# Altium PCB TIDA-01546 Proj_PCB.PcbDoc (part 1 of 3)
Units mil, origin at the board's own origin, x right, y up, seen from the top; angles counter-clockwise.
Board outline 2500 x 2000 mil, 2 copper layers (Top Layer, Bottom Layer), stack 62 mil thick; 176 components, 113 nets, 564 pads, 250 vias.
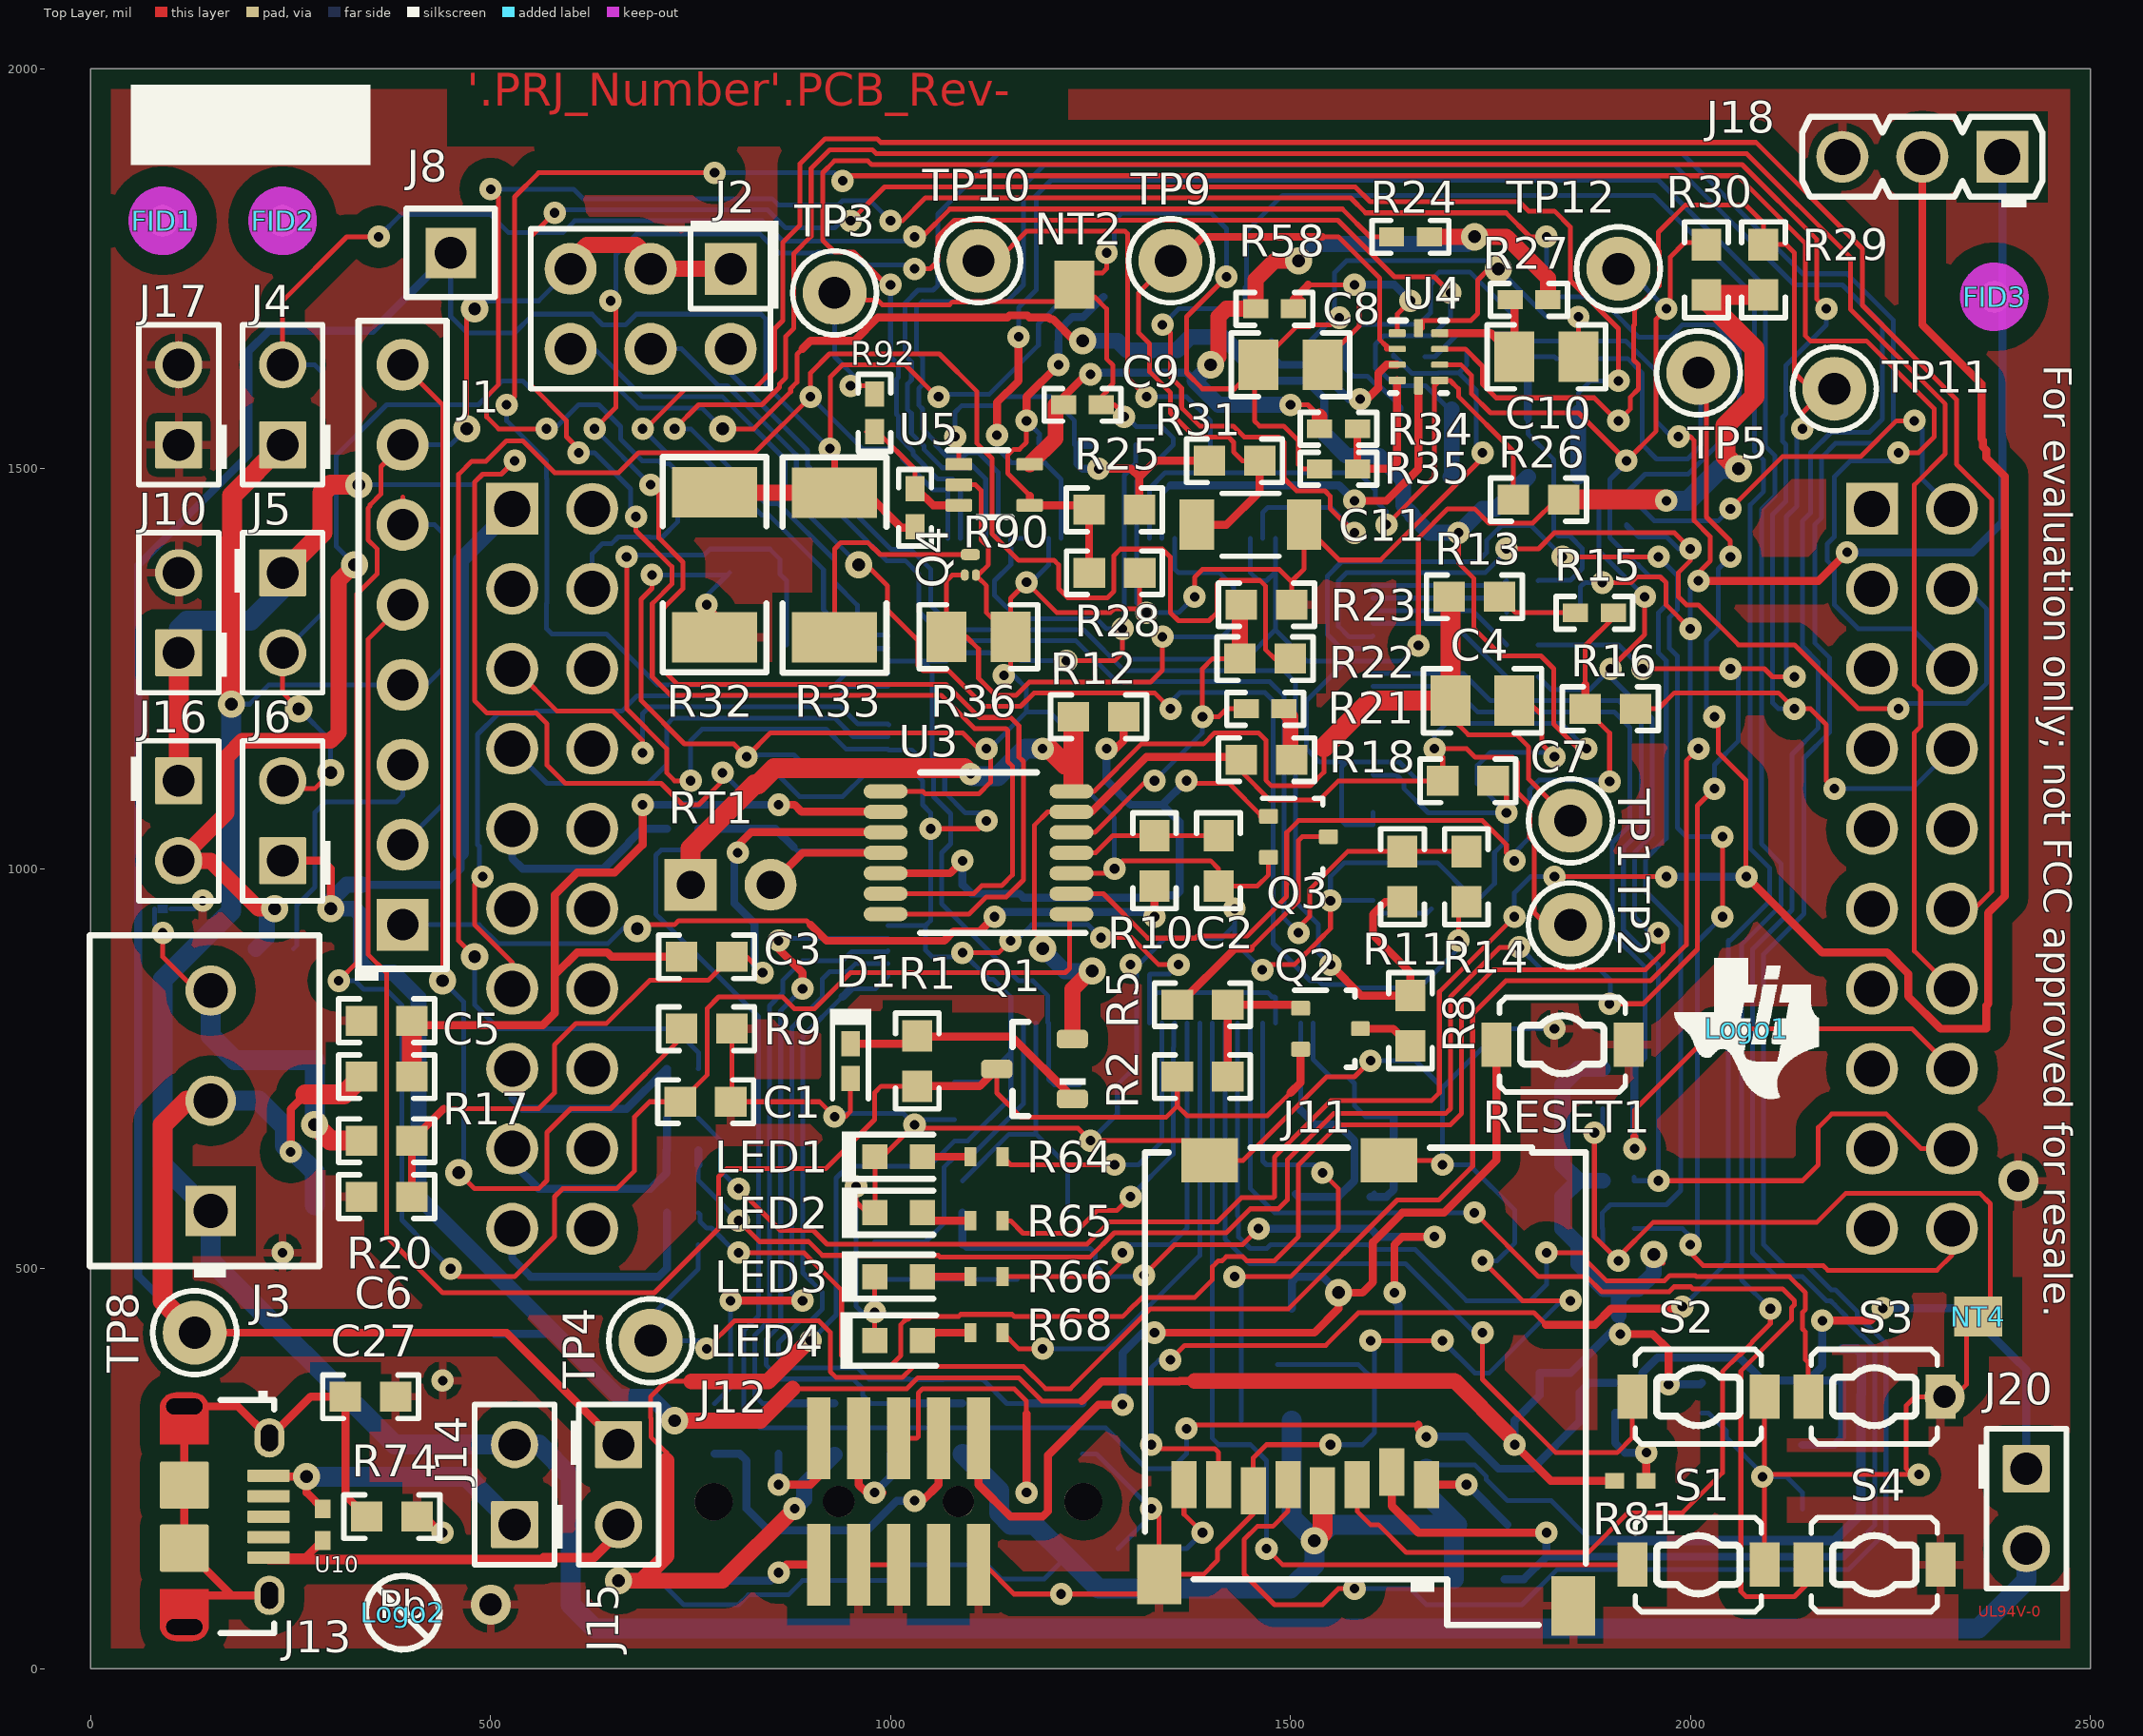
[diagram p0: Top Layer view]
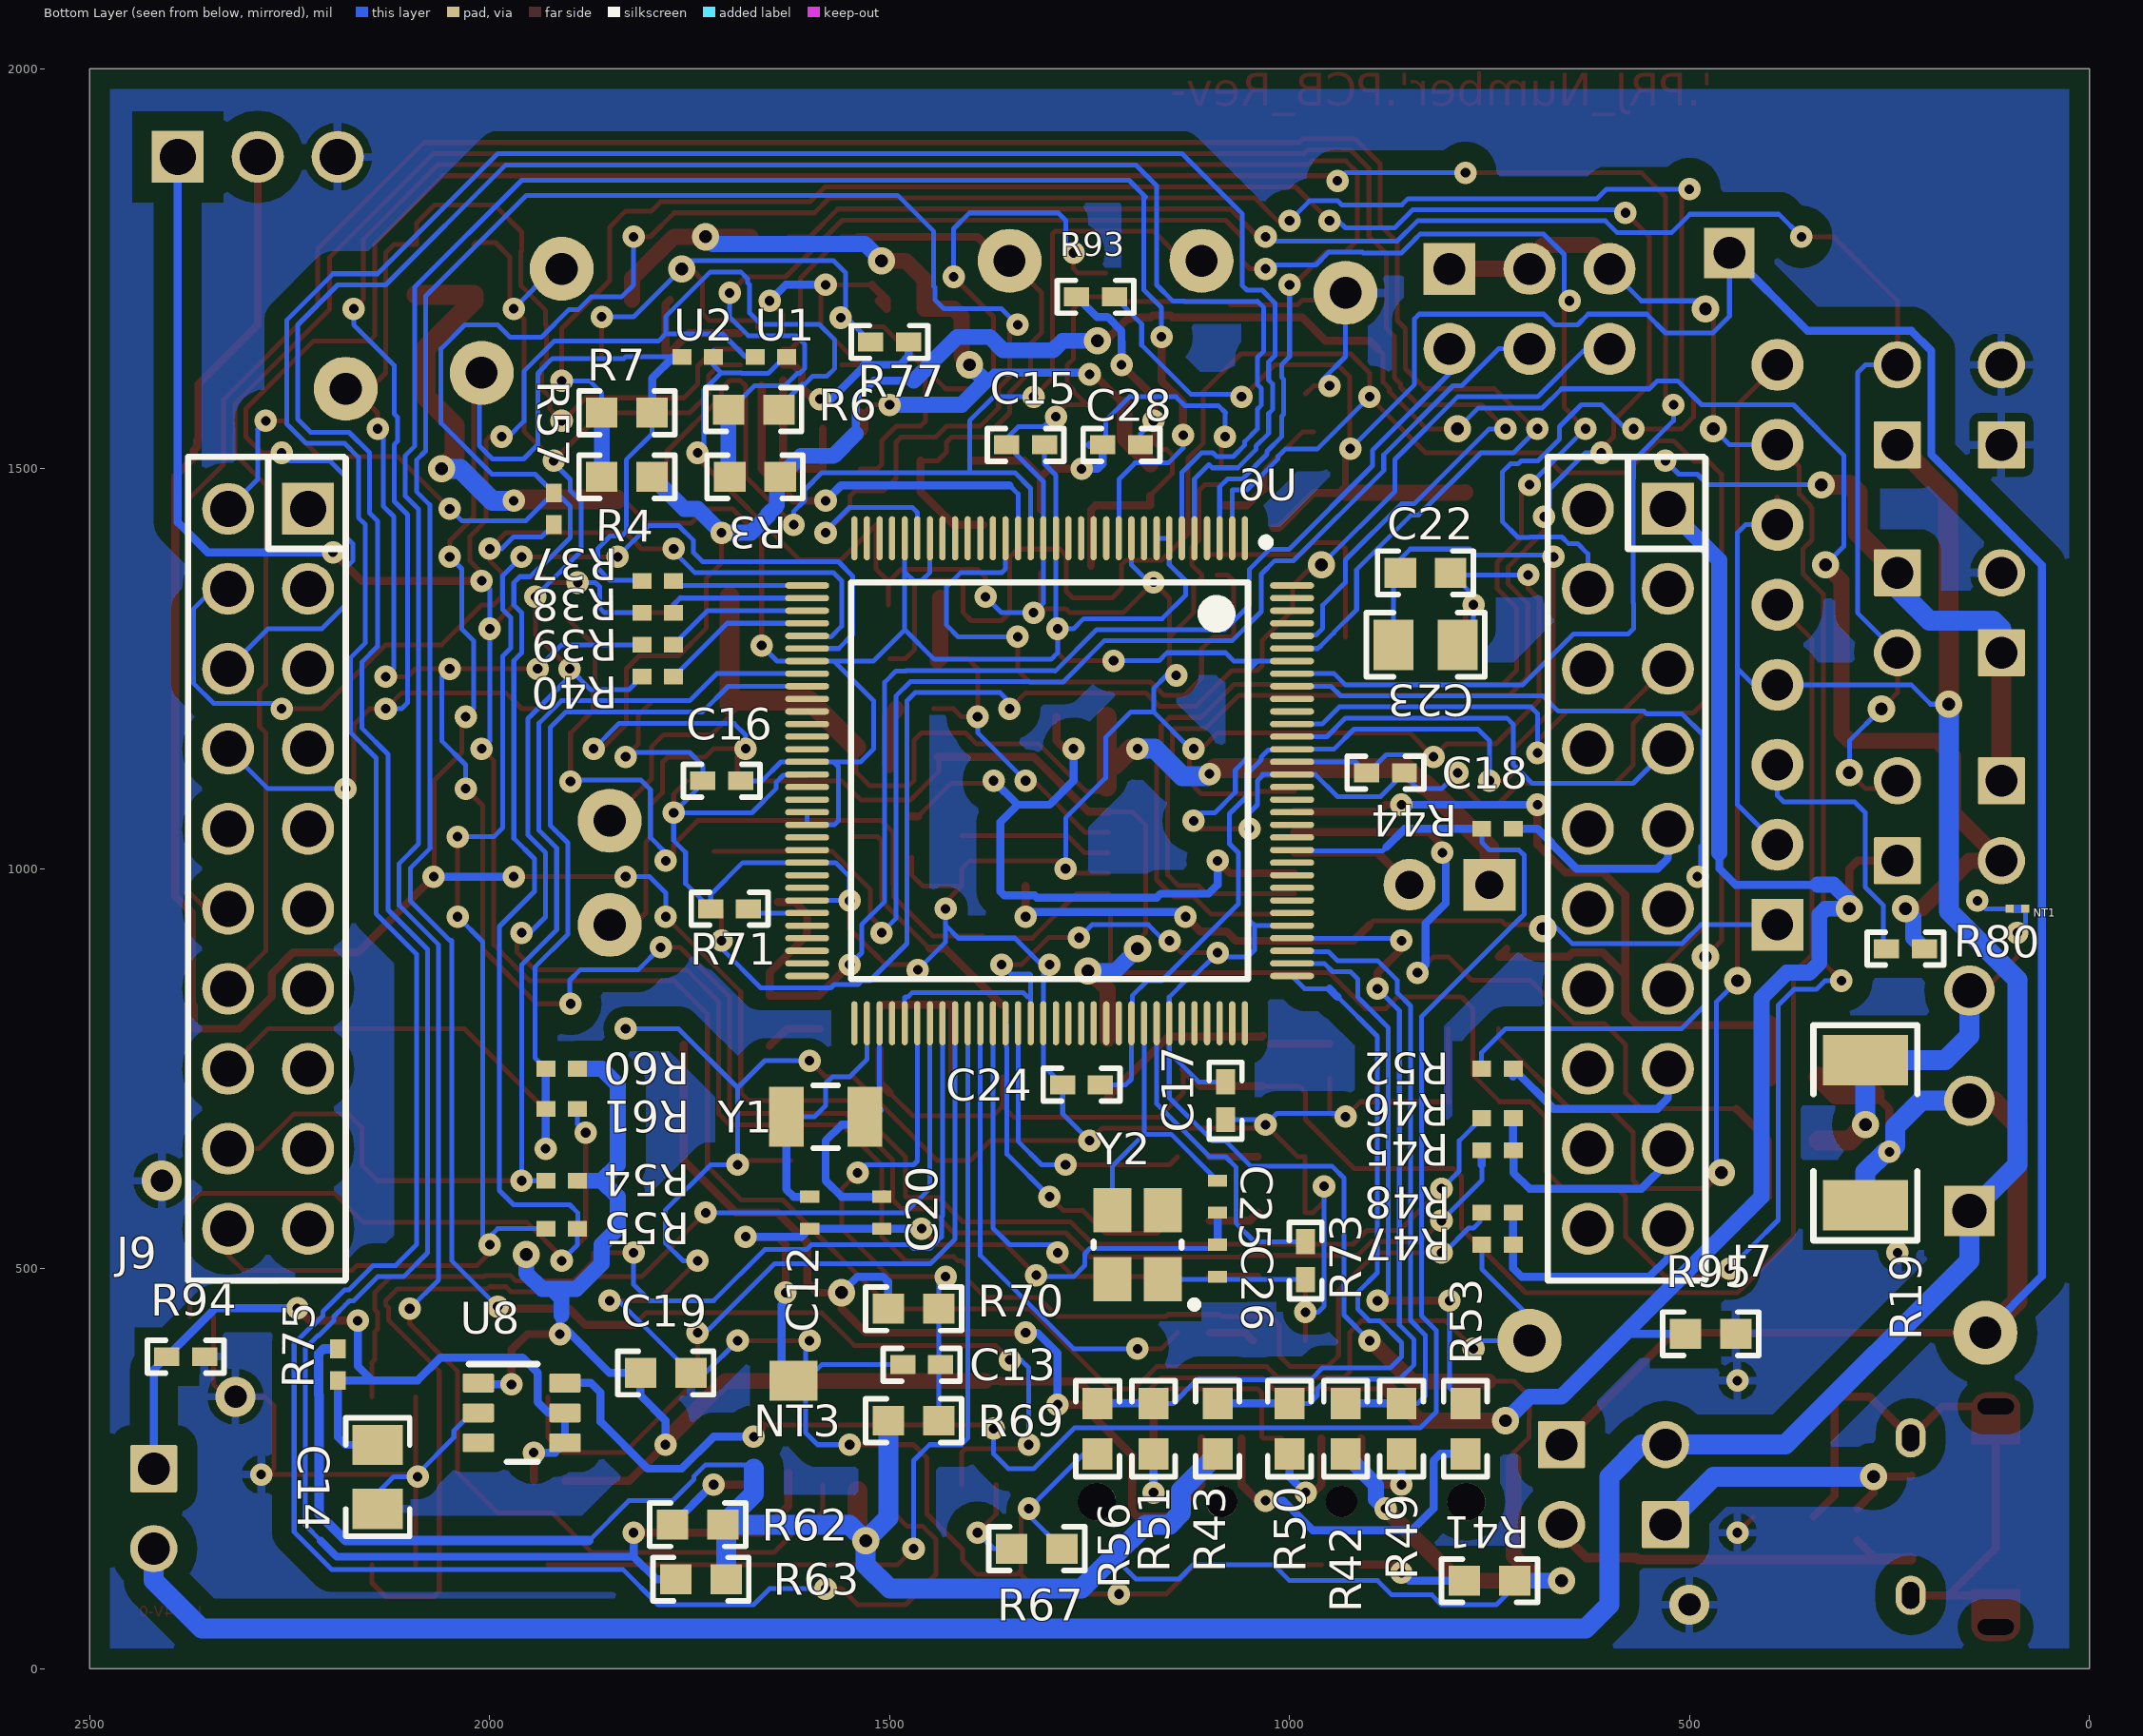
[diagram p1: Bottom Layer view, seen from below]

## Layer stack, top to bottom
Top Solder: solder mask 0.4, Solder Resist, Dk 3.5
Top Layer: signal copper 1.4
Dielectric1: core 59.2, FR-4, Dk 4.8
Bottom Layer: signal copper 1.4
Bottom Solder: solder mask 0.4, Solder Resist, Dk 3.5

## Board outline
0,0 2500,0 2500,2000 0,2000

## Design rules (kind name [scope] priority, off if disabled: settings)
AcuteAngle [All] p1: minimum=4.50000000000000E+0001 checktracksonly=FALSE
AssemblyTestPointUsage [All] p1: valid=2
BoardOutlineClearance BoardOutlineClearance_MountingHoles [OnCopper and InComponentClass('Mounting Holes')] p1: gap=40
BoardOutlineClearance BoardOutlineClearance_Poly [OnCopper and IsPoly] p2: gap=25
BoardOutlineClearance [OnCopper and Not InComponentClass('Logo') and not InComponentClass('FiducialMark') and not InRegion(1000,500,4000,800) and not InPoly] p3: gap=75 except(30: Arc-OutlineEdge Track-OutlineEdge SMDPad-OutlineEdge THPad-OutlineEdge Via-OutlineEdge Fill-OutlineEdge Poly-OutlineEdge Region-OutlineEdge Text-OutlineEdge)
Clearance Clearance_Keepouts [((IsTrack Or IsArc) And Not InPoly) And IsFree and IsKeepOut vs ((IsTrack Or IsArc) And Not InPoly) And IsFree and IsKeepOut] p1: gap=0
Clearance Clearance_Poly [InPolygon] p2: gap=25
Clearance Clearance_FiducialMark [IsKeepOut and InComponentClass('FiducialMark') vs IsPad and InComponentClass('FiducialMark')] p3: gap=0
Clearance [All] p4: gap=7.87
ComponentClearance ComponentClearance_MountingHoles_FiducialMarks [InComponentClass('Mounting Holes') vs InComponentClass('FiducialMark')] p1: gap=50 collisioncheckmode=3 verticalgap=10 showdistances=FALSE
ComponentClearance ComponentClearance_Shunt [InComponentClass('Header') vs InComponentClass('Shunt')] p2: gap=0 collisioncheckmode=3 verticalgap=0 showdistances=FALSE
ComponentClearance ComponentClearance_Logo [InComponentClass('Logo')] p3: gap=50 collisioncheckmode=3 verticalgap=10 showdistances=FALSE
ComponentClearance ComponentClearance_ScrewToNut [(HasFootprint('NY PMS 440 0025 PH')) vs (HasFootprint('Keystone_1902C'))] p4: gap=5 collisioncheckmode=3 verticalgap=10 showdistances=FALSE
ComponentClearance ComponentClearance_MountingHoles [InComponentClass('Mounting Holes')] p5: gap=250 collisioncheckmode=3 verticalgap=100000 showdistances=FALSE
ComponentClearance ComponentClearance_SmallPassives [HasFootprint('0201*') or HasFootprint('0402*') or HasFootprint('0508') or HasFootprint('0603*') or HasFootprint('0612') or HasFootprint('0805*') or HasFootprint('0815*') or HasFootprint('0830*') or HasFootprint('1206*') or HasFootprint('1210*') or HasFootprint('1808*') or HasFootprint('1812*') or HasFootprint('1825*') or HasFootprint('2010*') or HasFootprint('2220*') or HasFootprint('2225*') or HasFootprint('2512*') or HasFootprint('2728*') or HasFootprint('3518*') vs HasFootprint('0201*') or HasFootprint('0402*') or HasFootprint('0508') or HasFootprint('0603*') or HasFootprint('0612') or HasFootprint('0805*') or HasFootprint('0815*') or HasFootprint('0830*') or HasFootprint('1206*') or HasFootprint('1210*') or HasFootprint('1808*') or HasFootprint('1812*') or HasFootprint('1825*') or HasFootprint('2010*') or HasFootprint('2220*') or HasFootprint('2225*') or HasFootprint('2512*') or HasFootprint('2728*') or HasFootprint('3518*')] p6: gap=14.96 collisioncheckmode=3 verticalgap=10 showdistances=FALSE
ComponentClearance ComponentClearance_THtoSMT [IsThruComponent vs IsSMTComponent] p7: gap=40 collisioncheckmode=3 verticalgap=30 showdistances=FALSE
ComponentClearance ComponentClearance_THtoTH [IsThruComponent vs IsThruComponent] p8: gap=30 collisioncheckmode=3 verticalgap=30 showdistances=FALSE
ComponentClearance [All] p9: gap=30 collisioncheckmode=3 verticalgap=10 showdistances=FALSE
DiffPairsRouting [All] p1: maxlimit=100 minlimit=10 mostfreqgap=10 toplayer_minwidth=15 toplayer_maxwidth=15 toplayer_prefwidth=15 bottomlayer_minwidth=15 bottomlayer_maxwidth=15 bottomlayer_prefwidth=15 maxuncoupledlength=1000
FabricationTestPointUsage TestPointUsage [All] p1: valid=2 allowmultiple=FALSE
FabricationTestpoint Testpoint [All] p1: side=3 testpointundercomponent=TRUE minsize=40 maxsize=100 preferedsize=60 minholesize=0 maxholesize=40 preferedholesize=32 testpointgrid=1 allowsidetop=TRUE allowsidebottom=TRUE usegrid=TRUE gridtolerance=0.01
FanoutControl Fanout_LCC [IsLCC] p1: bgadir=Out bgaviamode=Centered fanoutstyle=Auto fanoutdirection=Alternating viagrid=1 // Fanout_LCC (Default Rule)
FanoutControl Fanout_BGA [IsBGA] p2: bgadir=Out bgaviamode=Centered fanoutstyle=Auto fanoutdirection=Alternating viagrid=1 // Fanout_BGA (Default Rule)
FanoutControl Fanout_Default [All] p4: bgadir=Out bgaviamode=Centered fanoutstyle=Auto fanoutdirection=Alternating viagrid=1 // Fanout_Default (Default Rule)
FanoutControl Fanout_Small [(CompPinCount < 5)] p5: bgadir=Out bgaviamode=Centered fanoutstyle=Auto fanoutdirection=OutThenIn viagrid=1 // Fanout_Small (Default Rule)
HoleSize [All] p1: absolutevalues=TRUE maxlimit=251 minlimit=7.87 maxpercent=80.000 minpercent=20.000
MinimumAnnularRing MinimumAnnularRing_ThermalPadVias [IsVia and InAnyComponent] p1: minimumring=5.91
MinimumAnnularRing [All] p2: minimumring=8
MinimumSolderMaskSliver MinimumSolderMaskSliver_Logo [InComponentClass('Logo') vs InComponentClass('Logo')] p1: minsoldermaskwidth=0.7
MinimumSolderMaskSliver [All] p2: minsoldermaskwidth=3.94
PlaneConnect [All] p1: planeconnectstyle=Relief reliefexpansion=10 reliefentries=4 reliefconductorwidth=10 reliefairgap=10
PolygonConnect [All] p1: connectstyle=Relief reliefconductorwidth=10 reliefentries=4 polygonreliefangle="90 Angle" airgapwidth=10
RoutingVias ThermalPadVias [IsVia and InAnyComponent] p1: holewidth=7.87 width=19.68 viastyle="Through Hole" minholewidth=7.87 minwidth=19.68 maxholewidth=12.99 maxwidth=23.62
RoutingVias [All] p2: holewidth=16 width=34 viastyle="Through Hole" minholewidth=7.87 minwidth=26 maxholewidth=40 maxwidth=65
SilkToBoardRegionClearance [Not ((IsComment or IsDesignator) And (Hide <> 'False')) and not InRegion(1000,500,4000,800)] p1:
SilkToSilkClearance SilkToSilkClearance_Pb-FreeLogo [(HasFootprint('Pb-Free_Overlay_Medium') OR HasFootprint('Pb-Free_Overlay_Small')) vs (HasFootprint('Pb-Free_Overlay_Medium') OR HasFootprint('Pb-Free_Overlay_Small'))] p1: silktosilkclearance=0
SilkToSilkClearance [All] p2: silktosilkclearance=4
SilkToSolderMaskClearance SilkToComponentPadClearance [(IsPad or IsFill or IsRegion) and InAnycomponent] p1: minsilkscreentomaskgap=5 clearancetoexposedcopper=TRUE
SilkToSolderMaskClearance "Silk to Solder Mask Opening" [All] p2: minsilkscreentomaskgap=4 clearancetoexposedcopper=FALSE
SolderMaskExpansion [All] p1: expansion=1.97
Width [All] p1: maxlimit=100 minlimit=6 preferedwidth=10 checkconnectedcopper=TRUE
15 further rules are at their usual default settings.

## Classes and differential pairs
component class AssemblyNote: ZZ1 ZZ2 ZZ3 ZZ4
component class FiducialMark: FID1 FID2 FID3
component class "TIDA-01546 Proj_EVM_Hardware": FID1 FID2 FID3 Logo1 Logo2 Logo3 ZZ1 ZZ2 ZZ3 ZZ4
component class Logo: Logo1
component class Header: J1 J2 J4 J5 J6 J10 J14 J15 J16 J17 J18 J20
component class "TIDA-01546 Proj_BatMonitoring": C1 C2 C3 C4 C5 C6 C7 D1 J1 J2 J3 J16 J18 NT1 Q1 Q2 Q3 R1 R2 R3 R4 R5 R6 R7 R8 R9 R10 R11 R12 R13 R14 R15 R16 R17 R18 R19 R20 R21 R22 R23 R80 RT1 TP1 TP2 TP3 TP4 TP5 TP8 U1 U2 U3
component class "TIDA-01546 Proj_SysLoad": C12 C13 C14 C15 C16 C17 C18 C19 C20 C22 C23 C24 C25 C26 C27 J7 J9 J10 J11 J12 J13 J14 J15 J17 J20 LED1 LED2 LED3 LED4 NT3 NT4 R37 R38 R39 R40 R41 R42 R43 R44 R45 R46 R47 R48 R49 R50 R51 R52 R53 R54 R55 R56 R57 R60 R61 R62 R63 R64 R65 R66 R67 R68 R69 R70 R71 R73 R74 R75 R81 R94 R95 RESET1 S1 S2 S3 S4 U6 U8 U10 Y1 Y2
component class "TIDA-01546 Proj_SysMonitoring": C8 C9 C10 C11 C28 J4 J5 J6 J8 NT2 Q4 R24 R25 R26 R27 R28 R29 R30 R31 R32 R33 R34 R35 R36 R58 R77 R90 R92 R93 TP9 TP10 TP11 TP12 U4 U5

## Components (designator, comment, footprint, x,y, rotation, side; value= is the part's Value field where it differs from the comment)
C1 "GRM188R71H332KA01D" 0603 768.7,708.7 r0 top
C2 "GRM188R71H104KA93D" 0603 1410,1010 r90 top
C3 "GRM188R71H104KA93D" 0603 770,890 r180 top
C4 "GRM21BR71H105KA12L" 0805_HV 1740,1210 r180 top
C5 "GRM188R71H104KA93D" 0603 370,810 r0 top
C6 "GRM188R71H104KA93D" 0603 370,590 r0 top
C7 "GRM188R71H104KA93D" 0603 1721.81,1110 r180 top
C8 "GRM21BR71H105KA12L" 0805_HV 1500,1630 r0 top
C9 "160R07X104KV4T" 0402_065 1240,1580 r0 top
C10 "GRM21BR71H105KA12L" 0805_HV 1820,1640 r180 top
C11 "202R18W102KV4E" 1206_190 1450,1430 r180 top
C12 "GRM1555C1H120JA01D" 0402S 1600,570 r270 bottom
C13 "160R07X104KV4T" 0402_065 1460,380 r180 bottom
C14 "0805YD105KAT2A" 0805_HV 2140,239.68 r90 bottom
C15 "GRM155R71C104KA88D" 0402 1330,1530 r180 bottom
C16 "GRM155R71C104KA88D" 0402 1710,1110 r180 bottom
C17 "GRM155R71C104KA88D" 0402 1080,710 r90 bottom
C18 "GRM155R71C104KA88D" 0402 880,1120 r180 bottom
C19 "C1608X7R1E104K080AA" 0603 1780,369.68 r0 bottom
C20 "GRM1555C1H120JA01D" 0402S 1510,570 r90 bottom
C22 "GRM188R61C225KE15D" 0603 830,1370 r0 bottom
C23 "0805YD105KAT2A" 0805_HV 830,1280 r0 bottom
C24 "GRM155R71C104KA88D" 0402 1260,730 r180 bottom
C25 "GRM1555C1H120JA01D" 0402S 1090,590 r270 bottom
C26 "GRM1555C1H120JA01D" 0402S 1090,510 r90 bottom
C27 "06035C332KAT2A" 0603 350,340 r180 top
C28 "0402YC101KAT2A" 0402 1210,1530 r180 bottom
D1 "BZT52C5V6T-7" SOD-523 950,759.69 r270 top
FID1 "Fiducial" Fiducial10-20 90,1810 r0 top
FID2 "Fiducial" Fiducial10-20 240,1810 r0 top
FID3 "Fiducial" Fiducial10-20 2380,1715 r0 top
J1 "PEC08SAAN" SULLINS_PEC08SAAN 390,1280 r90 top
J2 "PEC03DAAN" SULLINS_PEC03DAAN 700,1700 r180 top
J3 "39357-0003" Molex_39357-0003 150,710 r90 top
J4 "PEC02SAAN" CONN_PEC02SAAN 240,1580 r90 top
J5 "PEC02SAAN" CONN_PEC02SAAN 240,1320 r270 top
J6 "PEC02SAAN" CONN_PEC02SAAN 240,1060 r90 top
J7 "SSW-110-23-F-D" CONN_SSW-110-23-F-D 577,1000 r90 bottom
J8 "PEC01SAAN" Sullins_PEC01SAAN 450,1770 r90 top
J9 "SSW-110-23-F-D" CONN_SSW-110-23-F-D 2277,1000 r90 bottom
J10 "PEC02SAAN" CONN_PEC02SAAN 110,1320 r90 top
J11 "CMP-0075148-1" 3M_2908-05WB-MG 1670,230 r180 top
J12 "JTAG_ARM_10PIN" CON_2X5_50MIL 910,130 r0 top
J13 "10118194-0001LF" FCI_10118194-0001LF 60,190 r270 top
J14 "PEC02SAAN" CONN_PEC02SAAN 530,230 r90 top
J15 "PEC02SAAN" CONN_PEC02SAAN 660,230 r270 top
J16 "PEC02SAAN" CONN_PEC02SAAN 110,1060 r270 top
J17 "PEC02SAAN" CONN_PEC02SAAN 110,1580 r90 top
J18 "61300311121" WURTH_61300311121 2290,1890 r180 top
J20 "PEC02SAAN" CONN_PEC02SAAN 2420,200 r270 top
LED1 "LTST-C191KFKT" LTST-C191_Orange 1010,640 r180 top
LED2 "LTST-C191TGKT" LTST-C191_Green 1010,570 r180 top
LED3 "LTST-C190CKT" LED_LTST-C190_Red 1010,490 r180 top
LED4 "LTST-C193TBKT-5A" LTST-C193_Blue 1010,410 r180 top
Logo1 "Texas Instruments" TI_Symbol_Overlay_Small 2070,800 r0 top
Logo2 "Pb-Free Symbol" Pb-Free_Overlay_Small 390,70 r0 top
Logo3 "FCC disclaimer" FCC_disclaimer 3700,2600 r270 top
NT1 "Net-Tie" Net-Tie_10mil 90,950 r0 bottom net-tie
NT2 "Net-Tie" Net-Tie_50milWide_30milLong 1230,1730 r270 top net-tie
NT3 "Net-Tie" Net-Tie_50milWide_30milLong 1620,360 r180 bottom net-tie
NT4 "Net-Tie" Net-Tie_50milWide_30milLong 2360,440 r0 top net-tie
Q1 "2N7002-7-F" SOT-23 1180,749.69 r180 top
Q2 "BSS84W-7-F" SOT-323 1550,800 r0 top
Q3 "BSS138W-7-F" SOT-323 1510,1040 r0 top
Q4 "CSD13383F4" YJC0003A 1099.68,1380 r90 top
R1 "CRCW060310K0JNEA" 0603 1033.42,759.69 r90 top
R2 "CRCW0603100KFKEA" 0603 1390,740 r0 top
R3 "CRCW060310K0FKEA" 0603 1668.35,1490 r0 bottom
R4 "CRCW060310K0FKEA" 0603 1828.34,1490 r0 bottom
R5 "CRCW0603165KFKEA" 0603 1390,830 r180 top
R6 "CRCW0603100RFKEA" 0603 1670,1574 r180 bottom
R7 "CRCW0603100RFKEA" 0603 1828.35,1570 r180 bottom
R8 "RG1608P-164-B-T5" 0603 1650,810 r90 top
R9 "RG1608P-1652-B-T5" 0603 770,800 r0 top
R10 "CRCW0603100RFKEA" 0603 1330,1010 r90 top
R11 "RG1608P-9092-B-T5" 0603 1640,990 r90 top
R12 "CRCW0603100KFKEA" 0603 1260,1190 r0 top
R13 "CRCW0603100KFKEA" 0603 1730,1340 r0 top
R14 "RG1608P-9092-B-T5" 0603 1720,990 r90 top
R15 "RC0402JR-070RL" 0402 1880,1320 r0 top
R16 "CRCW06031K00JNEA" 0603 1900,1200 r0 top
R17 "CRCW0603100RFKEA" 0603 370,740 r0 top
R18 "CRCW060310K0FKEA" 0603 1470.16,1136.28 r0 top
R19 "WSL2010R1000FEA" 2010 280,670 r90 bottom
R20 "CRCW0603100RFKEA" 0603 370,660 r0 top
R21 "RC0402JR-070RL" 0402 1468.35,1200 r180 top
R22 "CRCW06031K00JNEA" 0603 1468.35,1262.68 r0 top
R23 "CRCW06031M00JNEA" 0603 1470,1330 r0 top
R24 "RC0402JR-070RL" 0402 1650,1790 r0 top
R25 "CRCW06032M20JNEA" 0603 1279.68,1448.7 r0 top
R26 "CRCW06031K00JNEA" 0603 1810,1461.46 r180 top
R27 "RC0402JR-070RL" 0402 1798.23,1711.34 r0 top
R28 "CRCW060347K0JNEA" 0603 1280,1370 r180 top
R29 "CRCW06031K00FKEA" 0603 2091.32,1748.7 r90 top
R30 "CRCW06031K00FKEA" 0603 2020,1748.7 r90 top
R31 "CRCW0603100KJNEA" 0603 1430,1510 r0 top
R32 "CRCW20106K80JNEF" 2010 780,1380 r270 top
R33 "WSL2010R1000FEA" 2010 930,1379.68 r270 top
R34 "RC0402JR-070RL" 0402 1560,1550 r0 top
R35 "RC0402JR-070RL" 0402 1560,1500 r180 top
R36 "CRCW0805330KJNEA" 0805_HV 1110,1290 r0 top
R37 "CRCW04020000Z0ED" 0402L 1790,1360 r180 bottom
R38 "CRCW04020000Z0ED" 0402L 1790,1320 r0 bottom
R39 "CRCW04020000Z0ED" 0402L 1790,1280 r180 bottom
R40 "CRCW04020000Z0ED" 0402L 1790,1240 r0 bottom
R41 "CRCW0603100RFKEA" 0603 750,110 r0 bottom
R42 "CRCW060310K0FKEA" 0603 929.93,300 r90 bottom
R43 "CRCW060310K0FKEA" 0603 1090,300 r90 bottom
R44 "CRCW04020000Z0ED" 0402L 740,1050 r180 bottom
R45 "CRCW04020000Z0ED" 0402L 740,648.19 r180 bottom
R46 "CRCW04020000Z0ED" 0402L 740,688.19 r180 bottom
R47 "CRCW04020000Z0ED" 0402L 740,530 r180 bottom
R48 "CRCW04020000Z0ED" 0402L 740,570 r180 bottom
R49 "CRCW060333R0FKEA" 0603 859.93,300 r90 bottom
R50 "CRCW060333R0FKEA" 0603 1000,300 r90 bottom
R51 "CRCW060333R0FKEA" 0603 1170,300 r90 bottom
R52 "CRCW04020000Z0ED" 0402L 740,750 r180 bottom
R53 "CRCW060333R0FKEA" 0603 780,300 r90 bottom
R54 "CRCW04024K70JNED" 0402L 1910,610 r0 bottom
R55 "CRCW04020000Z0ED" 0402L 1910,550 r0 bottom
R56 "CRCW060310K0FKEA" 0603 1240,300 r270 bottom
R57 "CRCW04020000Z0ED" 0402L 1920,1450 r270 bottom
R58 "RC0402JR-070RL" 0402 1480,1700 r180 top
R60 "CRCW04024K70JNED" 0402L 1910,750 r180 bottom
R61 "CRCW04020000Z0ED" 0402L 1910,700 r180 bottom
R62 "CRCW060310K0FKEA" 0603 1740,180 r0 bottom
R63 "CRCW060310K0FKEA" 0603 1735.99,111.89 r0 bottom
R64 "CRCW0402390RJNED" 0402S 1120,640 r180 top
R65 "CRCW0402390RJNED" 0402S 1120,560 r180 top
R66 "CRCW0402470RJNED" 0402S 1120,490 r180 top
R67 "CRCW060310K0FKEA" 0603 1315.9,150 r180 bottom
R68 "CRCW0402390RJNED" 0402S 1120,420 r180 top
R69 "CRCW060310K0FKEA" 0603 1470,310 r180 bottom
R70 "CRCW0603100RFKEA" 0603 1470,450 r0 bottom
R71 "ERA-2AEB4871X" 0402 1700,950 r0 bottom
R73 "ERJ-2RKF2001X" 0402 980,510 r270 bottom
R74 "CRCW06031M00JNEA" 0603 376.5,190 r0 top
R75 "CRCW04020000Z0ED" 0402L 2190,380 r270 bottom
R77 "RC0402JR-070RL" 0402 1500,1658.52 r180 bottom
R80 "RC0402JR-070RL" 0402 230,900 r0 bottom
R81 "CRCW04020000Z0ED" 0402L 1925,235 r180 top
R90 "RC0402JR-070RL" 0402 1030.63,1451.37 r90 top
R92 "RC0402JR-070RL" 0402 980,1570 r270 top
R93 "CRCW040247K0JNED" 0402 1242.5,1715 r0 bottom
R94 "CRCW040210M0JNED" 0402 2380,390 r0 bottom
R95 "CRCW0603100RFKEA" 0603 473.5,418.7 r0 bottom
RESET1 "TL1015AF160QG" SW_TL1015AF160QG 1840,780 r180 top
RT1 "103AT-2" Thermistor_103AT-2 800,980 r0 top
S1 "TL1015AF160QG" SW_TL1015AF160QG 2010,130 r180 top
S2 "TL1015AF160QG" SW_TL1015AF160QG 2010,340 r180 top
S3 "TL1015AF160QG" SW_TL1015AF160QG 2230,340 r180 top
S4 "TL1015AF160QG" SW_TL1015AF160QG 2230,130 r180 top
TP1 "5002" Keystone5002 1850,1060 r90 top
TP2 "5002" Keystone5002 1849.88,929.82 r90 top
TP3 "5002" Keystone5002 930,1720 r90 top
TP4 "5002" Keystone5002 700,410 r90 top
TP5 "5002" Keystone5002 2010,1620 r90 top
TP8 "5002" Keystone5002 130,420 r90 top
TP9 "5002" Keystone5002 1350,1760 r90 top
TP10 "5002" Keystone5002 1110,1760 r90 top
TP11 "5002" Keystone5002 2180,1600 r90 top
TP12 "5002" Keystone5002 1910,1750 r90 top
U1 "TPD1E10B06DPYR" DPY0002A 1648.35,1640 r180 bottom
U2 "TPD1E10B06DPYR" DPY0002A 1740,1640 r180 bottom
U3 "BQ35100PWR" PW0014A_N 1109.99,1019.99 r180 top
U4 "CMP-0065258-3" RUG0010A 1660,1640 r0 top
U5 "LPV521MG" DCK0005A_N 1129.68,1480 r0 top
U6 "TM4C129ENCPDTI3R" PDT0128A 1300,1110 r270 bottom
U8 "TPS22860DBVR" DBV0006A_N 1960,319.68 r180 bottom
U10 "TPD1E10B06DPYR" DPY0002A 290,180 r270 top
Y1 "ABS07-32.768KHZ-9-T" XTAL_ABS07 1580,690 r180 bottom
Y2 "NX3225GA-25.000M-STD-CRG-2" NDK_NX3225GA 1190,530 r0 bottom
ZZ1 "This Assembly Note is for PCB labels only" AssemblyNoteLabel 185,3938 r0 top
ZZ2 "These assemblies are ESD sensitive, ESD precautions shall be observed." AssemblyNote 185,3829.11 r0 top
ZZ3 "These assemblies must be clean and free from flux and all contaminants. Use of no clean flux is not acceptable." AssemblyNote 185,3740.56 r0 top
ZZ4 "These assemblies must comply with workmanship standards IPC-A-610 Class 2, unless otherwise specified." AssemblyNote 185,3652 r0 top

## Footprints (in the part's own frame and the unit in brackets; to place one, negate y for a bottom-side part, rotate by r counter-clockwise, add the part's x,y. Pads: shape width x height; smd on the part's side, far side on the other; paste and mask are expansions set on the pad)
3M_2908-05WB-MG [mm] "Connector, Micro SD, R/A, SMD"
  rect 0.8x1.5 smd: 1(0,0) 2(1.1,-0.4) 3(2.2,0) 4(3.3,0.2) 5(4.4,0) 6(5.5,0.2) 7(6.6,0) 8(7.7,0)
  rect 1.4x1.9 smd: S1(-4.66,3.85) S2(8.49,2.85)
  rect 1.8x1.4 smd: S3(6.89,-10.3) S4(1.19,-10.3)
  silkscreen extent -5.06,-10.7 8.94,4.45, body extent -5.06,-10.75 8.94,4.5, height 1.91
0402 [mm] "0402 from SM-752 data"
  rect 0.8x0.6 smd: 1(-0.6,0) 2(0.6,0)
  silkscreen extent -1.22,-0.52 1.22,0.52, body extent -0.55,-0.3 0.55,0.3, height 0.6
0402_065 [mm] "0402"
  rect 0.8x0.6 smd: 1(-0.6,0) 2(0.6,0)
  silkscreen extent -1.22,-0.52 1.22,0.52, body extent -0.55,-0.3 0.55,0.3, height 0.65
0402L [mm] "0402 from SM-752 data"
  rect 0.6x0.5 smd: 1(-0.5,0) 2(0.5,0)
  body extent -0.55,-0.3 0.55,0.3, height 0.6
0402S [mil] "Based on C0402S footprint from PADS legacy"
  rect 15x24 smd: 1(-20,0) 2(20,0)
  body extent -22,-12 22,12, height 24
0603 [mm] "0603 from SM-752 data"
  rect 1x0.95 smd: 1(-0.8,0) 2(0.8,0)
  silkscreen extent -1.52,-0.69 1.52,0.69, body extent -0.87,-0.47 0.87,0.47, height 1
0805_HV [mil] "0805 with 30mil clearance between pads"
  rect 50x63 smd: 1(-40,0) 2(40,0)
  silkscreen extent -74,-40 74,40, body extent -43,-29 43,29, height 57
1206_190 [mm] "1206_190"
  rect 1.1x1.6 smd: 1(-1.7,0) 2(1.7,0)
  silkscreen extent -0.9,-1 0.9,1, body extent -1.75,-0.95 1.75,0.95, height 1.9
2010 [mm] "Chip Capacitor, Body 5.08x2.54mm, IPC Medium Density"
  rect 1.6x2.7 smd: 1(-2.3,0) 2(2.3,0)
  silkscreen extent -3.42,-1.65 3.42,1.65, body extent -2.73,-1.45 2.73,1.45, height 1.66
AssemblyNote [mil] "Assembly Note"
AssemblyNoteLabel [mil] "Assembly Note for PCB Labels"
CON_2X5_50MIL [mm]
  round 1.2 hole 1.2: 1(-3.327,2) 1(8.407,2)
  round 1 hole 1: 1(0.64,2) 1(4.44,2)
  rect 0.74x2.6 smd: P1(0,0) P2(0,4.008) P3(1.27,0) P4(1.27,4.008) P5(2.54,0) P6(2.54,4.008) P7(3.81,0) P8(3.81,4.008) P9(5.08,0) P10(5.08,4.008)
CONN_PEC02SAAN [mm] "SULLINS"
  rrect7% 1.5x1.5 hole 1.016: 1(-1.27,0)
  round 1.5 hole 1.016: 2(1.27,0)
  silkscreen extent -2.54,-1.52 2.54,1.27, body extent -2.54,-1.27 2.54,1.27, height 8.38
CONN_SSW-110-23-F-D [mm] "SAMTEC"
  rect 1.65x1.65 hole 1.15: 1(11.43,-1.27)
  round 1.65 hole 1.15: 2(11.43,1.27) 3(8.89,-1.27) 4(8.89,1.27) 5(6.35,-1.27) 6(6.35,1.27) 7(3.81,-1.27) 8(3.81,1.27) 9(1.27,-1.27) 10(1.27,1.27) 11(-1.27,-1.27) 12(-1.27,1.27) 13(-3.81,-1.27) 14(-3.81,1.27) 15(-6.35,-1.27) 16(-6.35,1.27) 17(-8.89,-1.27) 18(-8.89,1.27) 19(-11.43,-1.27) 20(-11.43,1.27)
  silkscreen extent -13.08,-2.46 13.08,2.54, body extent -13,-2.51 13,2.54, height 8.59
DBV0006A_N [mm] "SOT23, 6-Leads, Body 2.9x1.6mm, Pitch 0.95mm, Lead Span 2.8mm, IPC Medium Density"
  rrect17% 1x0.6 smd: 1(-1.375,0.95) 2(-1.375,0) 3(-1.375,-0.95) 4(1.375,-0.95) 5(1.375,0) 6(1.375,0.95)
  silkscreen extent -1.68,-1.55 0.5,1.55, body extent -1.42,-1.46 1.42,1.46, height 1.12
DCK0005A_N [mm] "SOT353, 5-Leads, Body 2x1.3mm, Pitch 0.65mm, Lead Span 2.1mm, IPC Medium Density"
  rrect25% 0.85x0.4 smd: 1(-1.125,0.65) 2(-1.125,0) 3(-1.125,-0.65) 4(1.125,-0.65) 5(1.125,0.65)
  silkscreen extent -1.48,-1.02 0.55,1.1, body extent -1.14,-1 1.14,1, height 0.95
DPY0002A [mm] "R-PX2SON-N2"
  rect 0.6x0.5 smd: 1(-0.5,0) 2(0.5,0)
  body extent -0.55,-0.35 0.55,0.35, height 0.4
FCC_disclaimer [mil]
FCI_10118194-0001LF [mm] "USB-micro B USB 2.0, 0.65mm, 5 Pos, R/A, SMT"
  rrect25% 0.4x1.35 smd: 1(-1.3,4.125) 2(-0.65,4.125) 3(0,4.125) 4(0.65,4.125) 5(1.3,4.125)
  rrect100% 1.25x0.95 hole 0.55 slot 0.85 at 0 deg: 6(-2.5,4.15) 7(2.5,4.15)
  round 0 hole 0.5 slot 1.15 at 90 deg: 8(-3.5,1.45) 9(3.5,1.45)
  rrect7% 1.5x1.55 smd: 10(-1,1.45) 11(1,1.45)
  Top Layer region: 3.445,0.675 3.636,0.713 3.799,0.821 3.907,0.984 3.945,1.175 3.945,1.175 3.945,1.175 3.945,1.725 3.907,1.916 3.799,2.079 3.636,2.187 3.445,2.225 3.445,2.225 2.3,2.225 2.3,0.675
  Top Layer region: -3.445,0.675 -3.636,0.713 -3.799,0.821 -3.907,0.984 -3.945,1.175 -3.945,1.175 -3.945,1.175 -3.945,1.725 -3.907,1.916 -3.799,2.079 -3.636,2.187 -3.445,2.225 -3.445,2.225 -2.3,2.225 -2.3,0.675
  silkscreen extent -4,2.6 3.7,4.3, body extent -4.02,-1.23 4.03,4.35, height 2.72
Fiducial10-20 [mm]
  round 1 smd mask+0.5: 1(0,0)
  Top Layer keep-out circle w1.178: c0,0 r0.5
Keystone5002 [mil] "For Keystone 500x miniature loop terminals"
  round 80 hole 40: 1(0,0)
  silkscreen extent -52,-52 52,52, body extent -49,-49 49,49, height 182
LED_LTST-C190_Red [mm] "Lite-On"
  rect 0.8x0.8 smd: 1(-0.75,0) 2(0.75,0)
  silkscreen extent -1.1,-0.8 1.8,0.8, body extent -0.85,-0.45 0.85,0.45, height 0.9
LTST-C191_Green [mm] "Lite-On"
  rect 0.8x0.8 smd: 1(-0.75,0) 2(0.75,0)
  silkscreen extent -1.1,-0.8 1.8,0.8, body extent -0.85,-0.45 0.85,0.45, height 0.65
LTST-C191_Orange [mm] "SMD, 2-Leads, Body 1.6x0.8mm"
  rect 0.8x0.8 smd: 1(-0.75,0) 2(0.75,0)
  silkscreen extent -1.1,-0.8 1.8,0.8, body extent -0.85,-0.45 0.85,0.45, height 0.65
LTST-C193_Blue [mm] "SMD, 2-Leads, Body1.6x0.8mm"
  rect 0.8x0.8 smd: 1(-0.75,0) 2(0.75,0)
  silkscreen extent -1.2,-0.9 1.85,0.9, body extent -0.85,-0.45 0.85,0.45, height 0.45
Molex_39357-0003 [mm] "Terminal Block, 3.5 mm, 3x1, TH"
  rect 1.6x1.6 hole 1.1: 1(-3.5,0)
  round 1.6 hole 1.1: 2(0,0) 3(3.5,0)
  silkscreen extent -5.61,-3.45 5.25,3.84, body extent -5.25,-3.45 5.16,3.84, height 8.51
NDK_NX3225GA [mm] "NDK"
  rect 1.2x1.4 smd: 1(-0.8,1.1) 2(-0.8,-1.1) 3(0.8,-1.1) 4(0.8,1.1)
  silkscreen extent -1.9,-0.1 1.4,2, body extent -1.3,-1.65 1.3,1.65, height 0.9
Net-Tie_10mil [mil] "10mil net tie, no solder mask opening, no solder paste"
  rect 10x10 smd paste-5 mask-5: 1(-10,0) 2(10,0)
  Top Layer region: -6,5 6,5 6,-5 -6,-5
Net-Tie_50milWide_30milLong [mil] "50mil net tie, no solder mask opening, no solder paste"
  rect 30x50 smd paste-20 mask-20: 1(-15,0) 2(15,0)
Pb-Free_Overlay_Small [mil]
  silkscreen extent -46,-46 46,46
PDT0128A [mm] "Thin QFP, 128-Leads, Body 14x14mm, Pitch 0.4mm"
  oval 1.4x0.2 smd: 1(-7.7,6.2) 2(-7.7,5.8) 3(-7.7,5.4) 4(-7.7,5) 5(-7.7,4.6) 6(-7.7,4.2) 7(-7.7,3.8) 8(-7.7,3.4) 9(-7.7,3) 10(-7.7,2.6) 11(-7.7,2.2) 12(-7.7,1.8) 13(-7.7,1.4) 14(-7.7,1) 15(-7.7,0.6) 16(-7.7,0.2) 17(-7.7,-0.2) 18(-7.7,-0.6) 19(-7.7,-1) 20(-7.7,-1.4) 21(-7.7,-1.8) 22(-7.7,-2.2) 23(-7.7,-2.6) 24(-7.7,-3) 25(-7.7,-3.4) 26(-7.7,-3.8) 27(-7.7,-4.2) 28(-7.7,-4.6) 29(-7.7,-5) 30(-7.7,-5.4) 31(-7.7,-5.8) 32(-7.7,-6.2) 65(7.7,-6.2) 66(7.7,-5.8) 67(7.7,-5.4) 68(7.7,-5) 69(7.7,-4.6) 70(7.7,-4.2) 71(7.7,-3.8) 72(7.7,-3.4) 73(7.7,-3) 74(7.7,-2.6) 75(7.7,-2.2) 76(7.7,-1.8) 77(7.7,-1.4) 78(7.7,-1) 79(7.7,-0.6) 80(7.7,-0.2) 81(7.7,0.2) 82(7.7,0.6) 83(7.7,1) 84(7.7,1.4) 85(7.7,1.8) 86(7.7,2.2) 87(7.7,2.6) 88(7.7,3) 89(7.7,3.4) 90(7.7,3.8) 91(7.7,4.2) 92(7.7,4.6) 93(7.7,5) 94(7.7,5.4) 95(7.7,5.8) 96(7.7,6.2)
  oval 0.2x1.4 smd: 33(-6.2,-7.7) 34(-5.8,-7.7) 35(-5.4,-7.7) 36(-5,-7.7) 37(-4.6,-7.7) 38(-4.2,-7.7) 39(-3.8,-7.7) 40(-3.4,-7.7) 41(-3,-7.7) 42(-2.6,-7.7) 43(-2.2,-7.7) 44(-1.8,-7.7) 45(-1.4,-7.7) 46(-1,-7.7) 47(-0.6,-7.7) 48(-0.2,-7.7) 49(0.2,-7.7) 50(0.6,-7.7) 51(1,-7.7) 52(1.4,-7.7) 53(1.8,-7.7) 54(2.2,-7.7) 55(2.6,-7.7) 56(3,-7.7) 57(3.4,-7.7) 58(3.8,-7.7) 59(4.2,-7.7) 60(4.6,-7.7) 61(5,-7.7) 62(5.4,-7.7) 63(5.8,-7.7) 64(6.2,-7.7) 97(6.2,7.7) 98(5.8,7.7) 99(5.4,7.7) 100(5,7.7) 101(4.6,7.7) 102(4.2,7.7) 103(3.8,7.7) 104(3.4,7.7) 105(3,7.7) 106(2.6,7.7) 107(2.2,7.7) 108(1.8,7.7) 109(1.4,7.7) 110(1,7.7) 111(0.6,7.7) 112(0.2,7.7) 113(-0.2,7.7) 114(-0.6,7.7) 115(-1,7.7) 116(-1.4,7.7) 117(-1.8,7.7) 118(-2.2,7.7) 119(-2.6,7.7) 120(-3,7.7) 121(-3.4,7.7) 122(-3.8,7.7) 123(-4.2,7.7) 124(-4.6,7.7) 125(-5,7.7) 126(-5.4,7.7) 127(-5.8,7.7) 128(-6.2,7.7)
  silkscreen extent -7.7,-6.3 6.3,6.99, body extent -8,-8 8,8, height 1.07
PW0014A_N [mm] "TSOP, 14-Leads, Body 5x4.4mm, Pitch 0.65mm, IPC Medium Density"
  oval 1.4x0.45 smd: 1(-2.95,1.95) 2(-2.95,1.3) 3(-2.95,0.65) 4(-2.95,0) 5(-2.95,-0.65) 6(-2.95,-1.3) 7(-2.95,-1.95) 8(2.95,-1.95) 9(2.95,-1.3) 10(2.95,-0.65) 11(2.95,0) 12(2.95,0.65) 13(2.95,1.3) 14(2.95,1.95)
  silkscreen extent -3.4,-2.55 1.85,2.55, body extent -3.21,-2.5 3.21,2.5, height 1
RUG0010A [mm] "QFN, 10-Leads, Body 2x1.5mm. Pitch 0.5mm, TI Recommended"
  rrect40% 0.55x0.25 smd: 1(-0.675,0.75) 4(-0.675,-0.75) 6(0.675,-0.75) 9(0.675,0.75)
  rrect50% 0.55x0.2 smd: 2(-0.675,0.25) 3(-0.675,-0.25) 7(0.675,-0.25) 8(0.675,0.25)
  rrect33% 0.3x0.575 smd: 5(0,-0.913) 10(0,0.913)
  silkscreen extent -0.9,-1.15 0.9,1.15, body extent -0.77,-1.02 0.77,1.02, height 0.41
SOD-523 [mm] "NXP Semiconductor recommended land pattern, nominal STEP model"
  rect 0.8x0.6 smd paste-0.05: 1(-0.55,0) 2(0.55,0)
  silkscreen extent -1.65,-0.66 1.2,0.66, body extent -0.8,-0.4 0.8,0.4, height 0.72
SOT-23 [mm] "SOT23, 3-Leads, Body 2.9x1.3mm, Pitch 0.95mm, Lead Span 2.5mm, IPC Medium Density"
  rrect50% 1x0.6 smd: 1(-1.2,0.95) 2(-1.2,-0.95) 3(1.2,0)
  silkscreen extent -1.63,-1.5 0.7,1.5, body extent -1.16,-1.45 1.21,1.45, height 1
SOT-323 [mm] "Diodes Inc recommended land pattern.  2016-02-24"
  rrect21% 0.6x0.47 smd: 1(-0.95,0.65) 2(-0.95,-0.65) 3(0.95,0)
  silkscreen extent -1.14,-1.22 0.77,1.22, body extent -1.13,-1.13 1.12,1.12, height 1.13
Sullins_PEC01SAAN [mm] "SULLINS"
  rect 1.6x1.6 hole 1: 1(0,0)
  silkscreen extent -1.4,-1.4 1.4,1.4, body extent -1.3,-1.3 1.3,1.3, height 8.38
SULLINS_PEC03DAAN [mm] "SULLINS"
  rect 1.65x1.65 hole 1.016 mask+0: 1(-2.54,-1.27)
  round 1.65 hole 1.016 mask+0: 2(-2.54,1.27) 3(0,-1.27) 4(0,1.27) 5(2.54,-1.27) 6(2.54,1.27)
  silkscreen extent -4.06,-2.79 3.81,2.54, body extent -3.81,-2.54 3.81,2.54, height 8.38
SULLINS_PEC08SAAN [mm] "SULLINS"
  rect 1.65x1.65 hole 1: 1(-8.89,0)
  round 1.65 hole 1: 2(-6.35,0) 3(-3.81,0) 4(-1.27,0) 5(1.27,0) 6(3.81,0) 7(6.35,0) 8(8.89,0)
  silkscreen extent -10.67,-1.4 10.29,1.52, body extent -10.29,-1.33 10.29,1.33, height 8.38
SW_TL1015AF160QG [mm] "E-Switch"
  rect 0.95x1.4 smd: 1(-2.1,0) 2(2.1,0)
  silkscreen extent -2,-1.5 2,1.5, body extent -2.3,-1.5 2.3,1.5, height 2
Thermistor_103AT-2 [mil] "SEMITEC"
  rect 65x65 hole 35: 1(-50,0)
  round 65 hole 35: 2(50,0)
  body extent -78,-47 79,47, height 338
TI_Symbol_Overlay_Small [mil]
  silkscreen extent -90,-88 91,88
WURTH_61300311121 [mm] "Header, 2.54mm, 3x1, TH"
  rect 1.65x1.65 hole 1.15: 1(-2.54,0)
  round 1.65 hole 1.15: 2(0,0) 3(2.54,0)
  silkscreen extent -3.81,-1.27 3.81,1.6, body extent -3.81,-1.27 3.81,1.27, height 8.54
XTAL_ABS07 [mm] "ABRACON"
  rect 1.1x1.9 smd: 1(-1.25,0) 2(1.25,0)
  silkscreen extent -0.4,-1 0.4,1, body extent -1.65,-0.8 1.65,0.8, height 0.9
YJC0003A [mm] "TI"
  rrect50% 0.25x0.2 on Top Paste: 0(-0.325,-0.2) 0(-0.325,0.2)
  rrect80% 0.35x0.25 smd paste-0.13 mask-0.05: 1(-0.325,0.175) 2(-0.325,-0.175)
  rrect57% 0.35x0.6 smd paste-0.05 mask-0.05: 3(0.325,0)
  body extent -0.5,-0.3 0.5,0.3, height 0.35

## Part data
C1: "CAP, CERM, 3300 pF, 50 V, +/- 10%, X7R, 0603"
C2 C3 C5 C6 C7: "CAP, CERM, 0.1 µF, 50 V, +/- 10%, X7R, 0603"
C4 C8 C10: "CAP, CERM, 1 µF, 50 V, +/- 10%, X7R, 0805"
C9 C13: "CAP, CERM, 0.1 µF, 16 V,+/- 10%, X5R, 0402"
C11: "CAP, CERM, 1000 pF, 2000 V,+/- 10%, X7R, 1206"
C12 C20 C25 C26: "CAP, CERM, 12 pF, 50 V, +/- 5%, C0G/NP0, 0402"
C14 C23: "CAP, CERM, 1 µF, 16 V,+/- 10%, X5R, 0805"
C15 C16 C17 C18 C24: "CAP, CERM, 0.1 µF, 16 V,+/- 10%, X7R, 0402"
C19: "CAP, CERM, 0.1 µF, 25 V,+/- 10%, X7R, 0603"
C22: "CAP, CERM, 2.2 µF, 16 V,+/- 10%, X5R, 0603"
C27: "CAP, CERM, 3300 pF, 50 V,+/- 10%, X7R, 0603"
C28: "CAP, CERM, 100 pF, 16 V,+/- 10%, X7R, 0402"
D1: "Diode, Zener, 5.6 V, 300 mW, SOD-523"
FID1 FID2 FID3: "Fiducial mark.  There is nothing to buy or mount."
J1: "Header, 100mil, 8x1, Tin, TH"
J2: "Header, 100mil, 3x2, Tin, TH"
J3: "Terminal Block, 3.5 mm, 3x1, Tin, TH"
J4 J5 J6 J10 J14 J15 J16 J17 J20: "Header, 100mil, 2x1, Tin, TH"
J7 J9: "Connector, Receptacle, 100mil, 10x2, Gold plated, TH"
J8: "Header, 1x1, Tin, TH"
J11: "Connector, Micro SD, R/A, SMD"
J13: "Receptacle, USB 2.0, Micro-USB Type B, R/A, SMT"
J18: "Header, 2.54 mm, 3x1, Gold, TH"
LED1: "LED, Orange, SMD"
LED2: "LED, Green, SMD"
LED3: "LED, Red, SMD"
LED4: "LED, Blue, SMD"
Logo1: library part TI_Logo, "Texas Instrument Corporate Signature"
Logo2: library part Pb-Free
Logo3: library part FCC_disclaimer, "FCC_disclaimer"
NT1 NT2 NT3 NT4: "Single point connection between nets."
Q1: "MOSFET, N-CH, 60 V, 0.17 A, SOT-23"
Q2: "MOSFET, P-CH, -50 V, -0.13 A, SOT-323"
Q3: "MOSFET, N-CH, 50 V, 0.2 A, SOT-323"
Q4: "MOSFET, N-CH, 12 V, 2.9 A, YJC0003A (PICOSTAR-3)"
R1: "RES, 10k ohm, 5%, 0.1W, 0603"
R2 R12 R13: "RES, 100 k, 1%, 0.1 W, 0603"
R3 R4 R18 R42 R43 R56 R62 R63 R67 R69: "RES, 10.0 k, 1%, 0.1 W, 0603"
R5: "RES, 165 k, 1%, 0.1 W, 0603"
R6 R7 R10 R17 R20 R41 R70 R95: "RES, 100, 1%, 0.1 W, 0603"
R8: "RES, 160 k, 0.1%, 0.1 W, 0603"
R9: "RES, 16.5 k, 0.1%, 0.1 W, 0603"
R11 R14: "RES, 90.9 k, 0.1%, 0.1 W, 0603"
R15 R21 R24 R27 R34 R35 R37 R38 R39 R40 R44 R45 R46 R47 R48 R52 R55 R57 R58 R61 R75 R77 R80 R81 R90 R92: "RES, 0, 5%, 0.063 W, 0402"
R16 R22 R26: "RES, 1.0k ohm, 5%, 0.1W, 0603"
R19 R33: "RES, 0.1, 1%, 0.5 W, 2010"
R23 R74: "RES, 1.0 M, 5%, 0.1 W, 0603"
R25: "RES, 2.2 M, 5%, 0.1 W, 0603"
R28: "RES, 47 k, 5%, 0.1 W, 0603"
R29 R30: "RES, 1.00 k, 1%, 0.1 W, 0603"
R31: "RES, 100 k, 5%, 0.1 W, 0603"
R32: "RES, 6.8 k, 5%, 0.75 W, AEC-Q200 Grade 0, 2010"
R36: "RES, 330 k, 5%, 0.125 W, 0805"
R49 R50 R51 R53: "RES, 33.0, 1%, 0.1 W, 0603"
R54 R60: "RES, 4.7 k, 5%, 0.063 W, 0402"
R64 R65 R68: "RES, 390, 5%, 0.063 W, 0402"
R66: "RES, 470, 5%, 0.063 W, 0402"
R71: "RES, 4.87 k, 0.1%, 0.062 W, AEC-Q200 Grade 0, 0402"
R73: "RES, 2.00 k, 1%, 0.1 W, AEC-Q200 Grade 0, 0402"
R93: "RES, 47 k, 5%, 0.063 W, 0402"
R94: "RES, 10 M, 5%, 0.063 W, 0402"
RESET1 S1 S2 S3 S4: "Switch, Tactile, SPST-NO, 0.05A, 12V, SMT"
RT1: "Thermistor NTC, 10.0k ohm, 1%, Disc, 5x8.4 mm"
TP1 TP2 TP3 TP4 TP5 TP8 TP9 TP10 TP11 TP12: "Test Point, Miniature, White, TH"
U1 U2 U10: "ESD in 0402 Package with 10 pF Capacitance and 6 V Breakdown, 1 Channel, -40 to +125 degC, 2-pin X2SON (DPY), Green (RoHS & no Sb/Br)"
U3: "Single Lithium Primary State-of-Health and End-of-Service Monitor, PW0014A"
U4: "Nanopower, Ultra-Small Size, Sensor Monitor with I2C Interface and Alert Output, RUG0010A (X2QFN-10)"
U5: "Nanopower 400nA, 1.8V, R-R I/O CMOS Op Amp, DCK0005A"
U6: "IoT enabled High performance 32-bit ARM(R) Cortex(R)-M4F based MCU, PDT0128A (TQFP-128)"
U8: "TPS22860 Ultra-low leakage load switch, DBV0006A (SOT-23-6)"
Y1: "CRYSTAL, 32.768KHZ, 9PF, SMD"
Y2: "Crystal, 25 MHz, 8pF, SMD"
ZZ1: library part AssemblyNoteLabel
ZZ2 ZZ3 ZZ4: library part AssemblyNote

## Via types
v1: diameter 28, hole 12, Top Layer to Bottom Layer, 217 vias
v2: diameter 34, hole 16, Top Layer to Bottom Layer, 30 vias
v3: diameter 50, hole 28, Top Layer to Bottom Layer, 3 vias

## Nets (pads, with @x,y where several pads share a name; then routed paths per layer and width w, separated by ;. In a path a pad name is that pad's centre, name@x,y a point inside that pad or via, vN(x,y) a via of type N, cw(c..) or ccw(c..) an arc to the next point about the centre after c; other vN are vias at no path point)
+3V3_DBG: C15.2 C16.2 C17.2 C18.2 J5.1 J10.1 J11.4 J16.1 R26.1 R29.1 R30.1 R41.1 R42.1 R43.1 R62.1 R63.1 R69.1 R75.1 U6.7 U6.8 U6.16 U6.26 U6.28 U6.39 U6.47 U6.51 U6.52 U6.69 U6.79 U6.90 U6.101 U6.113 U6.122 | length 10043
  Top Layer w6: v1(530,1510) 513.35,1493.35 490.02,1493.35 480,1483.34 480,1210 495.33,1194.67 557,1194.67 570.35,1181.31 570.35,1129.65 593.35,1106.65 713.1,1106.65 739.75,1080 760,1080 790,1110 v1(790,1120) ; 720,260 720,270 700.4,289.6 700.4,313.22 700,313.62 700,340 719.13,359.13 750.87,359.13 ; v1(1050,1050) 1110,1050 v1(1120,1060) ; v1(1090,894.87) 1135.12,894.87 v1(1150,909.76) ; v1(1220,1260) 1280,1260 1290,1270 v1(1290,1300) ; v1(1263.29,913.84) 1301.33,913.84 1335.18,880 v1(1360,880) ; v1(1660,1278.98) 1660,1413.42 1696.58,1450 1730,1450 1748.12,1431.88 1802.69,1431.88 1832.27,1461.46 R26.1@1841.5,1461.46
  Top Layer w20: v2(660,110) 688.8,110 ; 720,260 720,141.2 688.8,110 ; 750.87,359.13 847.16,359.13 898.03,410 v1(900,410) ; v1(880,200) 790,110 688.8,110
  Top Layer w25: J16.1@110,1110 J10.1@110,1270 ; J5.1@240,1370 290,1420 290,1470 300,1480 v2(335,1480) ; v2(1530,160) 1540.08,170.08 J11.4@1540.08,222.13 ; R26.1@1841.5,1461.46 1968.54,1461.46 v1(1970,1460) ; v2(2060,1500) 2043.98,1516.02 2043.98,1553.98 2080,1590 2080,1650 2020,1710 R30.1@2020,1717.2 R29.1@2091.32,1717.2
  Bottom Layer w6: v2@337.5,1480 476.66,1480 490.02,1493.35 513.35,1493.35 v1(530,1510) ; R41.1@718.5,110 718.5,102.95 741.46,80 809.98,80 822.17,92.18 872.18,92.18 890,110 1000,110 1020,130 1120.45,130 1138.33,112.13 1192.13,112.13 1220,140 ; v1(790,1120) 810,1100 839.5,1100 856.38,1116.88 C18.2@856.38,1120 886.38,1090 940,1090 967.87,1117.87 U6.113@996.85,1117.87 1034.09,1117.87 1034.09,1115.91 1040,1110 1040,1080 1050,1070 v1(1050,1050) 1050,935.18 1043.72,928.9 ; v1(900,410) 931.98,441.98 931.98,613.3 946.55,627.87 1048.25,627.87 1080.14,659.76 1096.32,659.76 1150.39,713.83 1150.39,770.39 ; U6.101@996.85,928.9 1043.72,928.9 ; U6.122@996.85,1259.61 1040,1259.61 ; C17.2@1080,733.62 1113.62,733.62 1150.39,770.39 ; v1(1120,1060) 1110,1070 1093.49,1070 1067.75,1095.75 1067.75,1123.46 1055.13,1136.08 1055.13,1136.84 1051.97,1140 1051.97,1247.64 1040,1259.61 ; v1(1150,909.76) 1156.22,909.76 1176.46,930 1247.14,930 v1(1263.29,913.84) ; U6.8@1166.14,1413.15 U6.7@1150.39,1413.15 1150.39,1380.39 1130,1360 1130,1341.81 1159.19,1312.62 1257.38,1312.62 1270,1300 v1(1290,1300) ; v1@1210,1260 1163.31,1260 1153.31,1270 1080,1270 1069.61,1259.61 1040,1259.61 ; C15.2@1306.38,1530 1306.38,1506.38 1292.13,1492.13 U6.16@1292.13,1413.15 1292.13,1302.13 v1(1290,1300) ; U6.79@1323.62,806.85 1323.62,840 ; v1(1360,880) 1348.44,868.45 1324.87,868.45 1323.62,867.19 1323.62,840 ; U6.26@1449.61,1413.15 1449.61,1370.39 1460,1360 1470,1360 1480,1370 1481.1,1370 ; U6.69@1481.1,806.85 1481.1,838.9 1480,840 1476.77,840 1471.49,845.28 1333.24,845.28 1327.95,840 1323.62,840 ; U6.28@1481.1,1413.15 1481.1,1370 ; U6.51@1603.15,1070.63 U6.52@1603.15,1054.88 1568.99,1054.88 1563.87,1060 1563.87,1127.5 1570,1133.62 ; v1(1660,1278.98) 1640.63,1259.61 U6.39@1603.15,1259.61 1569.61,1259.61 ; 1670,250 1674.87,254.87 1730.3,254.87 1744.87,240.3 1744.87,236.33 1771.2,210 1825.9,210 1875.9,160 ; C16.2@1686.38,1110 1659.46,1110 1635.84,1133.62 U6.47@1603.15,1133.62 1570,1133.62 ; 1043.72,928.9 1043.72,898.25 1051.97,890 1085.13,890 v1(1090,894.87) 1122.91,861.97 1128.03,861.97 1150.39,839.61 U6.90@1150.39,806.85 1150.39,770.39 ; v1(1290,1300) 1290,1270 1298.29,1261.71 1444.02,1261.71 1481.1,1298.79 ; 1481.1,1298.79 1520.29,1259.61 1569.61,1259.61 ; 1481.1,1298.79 1481.1,1370 ; 1569.61,1259.61 1520,1210 1520,1150 1536.38,1133.62 1570,1133.62
  Bottom Layer w10: R42.1@929.93,267.52 R42.1@929.93,268.5
  Bottom Layer w12: 1875.9,160 2180,160 2213.13,193.13 2213.13,342.17 2213.72,342.76 2213.72,393.72 2207.75,399.68 R75.1@2190,399.68
  Bottom Layer w20: v2(660,110) R41.1@718.5,110 ; v1(880,200) 891.87,211.87 891.87,229.46 R42.1@929.93,267.52
  Bottom Layer w25: J10.1@110,1270 110,1300 120,1310 200,1310 240,1350 J5.1@240,1370 ; R43.1@1090,268.5 1135.63,222.88 1135.63,194.37 1150,180 1180,180 1220,140 1260,100 1500,100 1530,130 v2(1530,160) ; R69.1@1501.5,310 1501.5,188.5 v2(1530,160) ; 1670,250 1670,218.5 R62.1@1708.5,180 ; R63.1@1704.49,111.89 1704.49,175.99 R62.1@1708.5,180 ; v1(1970,1460) 1996.87,1460 2036.87,1500 v2(2060,1500) ; v2(1530,160) 1550,180 R62.1@1708.5,180
ADDR: R34.2 R35.1 U4.4 | length 205.5
  Top Layer w10: R34.2@1583.62,1550 R35.1@1583.62,1500 1625.2,1500 1633.43,1508.23 U4.4@1633.43,1610.47
ADS_SCL: R29.2 R39.1 R45.1 TP11.1 U4.8 | length 3734.5
  Top Layer w6: v1(810,560) 836.13,533.87 897.63,533.87 914.88,516.62 1059.78,516.62 1061.59,514.81 1249.63,514.81 1279.7,544.87 1419.7,544.87 1449.7,574.87 1484.87,574.87 1496.13,586.13 1496.13,636.13 1553.87,693.87 1693.87,693.87 1700,700 1700,840 1761.75,901.75 v1(1786.22,901.75) ; U4.8@1686.57,1649.84 1718.5,1649.84 1740,1628.34 1740,1606 1757.3,1588.7 1879.63,1588.7 1908.33,1560 v1(1910,1560) 1925,1575 1925,1589.82 1934.87,1599.7 1934.87,1630.18 1929.04,1636.01 1929.04,1679.04 1930,1680 1930,1698.05 1960.87,1728.93 1960.87,1771.95 1960,1772.82 1960,1795.93 1994.07,1830 2068.68,1830 2091.32,1807.36 R29.2@2091.32,1780.2 2119.8,1780.2 2130,1770 2130,1620 2150,1600 2170,1600 2140,1570 v1(2140,1550) ; v1(1898.95,831.18) 1940.8,831.18 2008.75,899.13 2008.75,1078.75 v1(2030,1100) ; v1(1940,1250) v1(2050,1250) 2092.62,1250 2102.62,1240 v1(2130,1240)
  Bottom Layer w6: 759.68,629.68 759.68,610.32 v1(810,560) ; v1(1786.22,901.75) 1814.09,873.87 1886.68,873.87 1900,860.56 1900,832.23 v1(1898.95,831.18) ; R39.1@1809.68,1280 1910,1280 v1(1940,1250) ; v1(2030,1100) 2030,1130 2060,1160 2060,1240 v1(2050,1250) ; v1(2130,1240) 2120,1250 2120,1440.38 2133.14,1453.52 2133.14,1543.14 v1(2140,1550) v1@2137.63,1550 ; v1@2133.14,1553.14 v1@2133.82,1553.82
  Bottom Layer w10: 759.68,629.68 R45.1@759.68,648.19
ADS_SDA: R30.2 R40.2 R48.1 TP12.1 U4.7 | length 3285.3
  Top Layer w6: v1(810,520) 891.89,520 938.75,473.14 938.75,391.25 952.25,377.75 999.24,377.75 1012.91,391.41 1012.91,430.25 1019.28,436.62 1021.81,436.62 1025.19,440 1085.12,440 1088,442.87 1152,442.87 1154.88,440 1290,440 1305.06,455.06 1305.43,455.06 1314.25,463.87 1380,463.87 1402.36,486.24 1402.36,502.36 1410,510 1414.82,510 1419.7,514.87 1440.3,514.87 1445.18,510 1480,510 1510,540 1510,630 1560,680 1700,680 1713.87,693.87 1713.87,833.87 1753.87,873.87 1943.87,873.87 1966.13,896.13 1966.13,913.87 v1(1960,920) ; U4.7@1686.57,1630.16 1712.91,1630.16 1726.13,1616.94 1726.13,1593.87 1750,1570 1860,1570 v1(1920,1510) 1957.13,1547.13 1957.13,1687.13 v1(1970,1700) 1974.75,1704.75 1974.75,1764.75 1992.7,1782.7 2017.5,1782.7 R30.2@2020,1780.2 ; v1@1900,1240 v1(1900,1250) 1942.88,1292.88 v1(1942.88,1340)
  Bottom Layer w6: R48.1@759.68,570 761.65,568.03 761.65,559.06 770,550.72 776,550.72 806.72,520 v1(810,520) ; R40.2@1809.69,1240 1825.81,1223.87 1873.87,1223.87 v1(1900,1250) 1900,1240 1952.25,1187.75 1952.25,1042.25 1930.13,1020.13 1930.13,939.67 1949.8,920 v1(1960,920) ; TP12.1@1910,1750 1920,1750 v1(1970,1700) ; v1(1920,1510) 1920,1507.43 1899.28,1486.72 1899.28,1472.68 1885.41,1458.81 1885.41,1397.47 v1(1942.88,1340) v1@1950,1332.88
